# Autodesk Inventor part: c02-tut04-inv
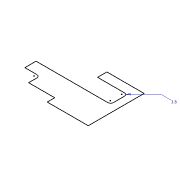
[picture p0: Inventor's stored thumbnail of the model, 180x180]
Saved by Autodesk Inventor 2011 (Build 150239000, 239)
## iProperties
Created: 2009-04
Part Number: c02-tut04-inv
Document SubType Name: Modeling
Designer: Sham
Density: 1 g/cm^3
Author: Sham
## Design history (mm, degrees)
sketch "Sketch1"
  geometry: L1 (22, 0)-(22, 30); L2 (22, 30)-(2, 30); L3 (2, 30)-(2, 25); L4 (2, 25)-(16.5, 25); L5 (18, 23.5)-(18, 17.5); L6 (16.5, 16)-(-22, 16); L7 (-22, 16)-(-22, 10); L8 (-22, 10)-(-15.5, 10); L9 (-14, 8.5)-(-14, 4); L10 (-14, 4)-(0, 4); L11 (0, 4)-(0, 0); L12 (0, 0)-(22, 0); A1 r 1.5 centre (16.5, 23.5) between (18, 23.5) and (16.5, 25); A2 r 1.5 centre (16.5, 17.5) between (16.5, 16) and (18, 17.5); A3 r 1.5 centre (-15.5, 8.5) between (-14, 8.5) and (-15.5, 10)
  constraints: 24 end point, 6 point on circle, 6 tangent, 3 centre point, 2 equal radius
  dimensions: "d0" = 1.5 radius of A1
